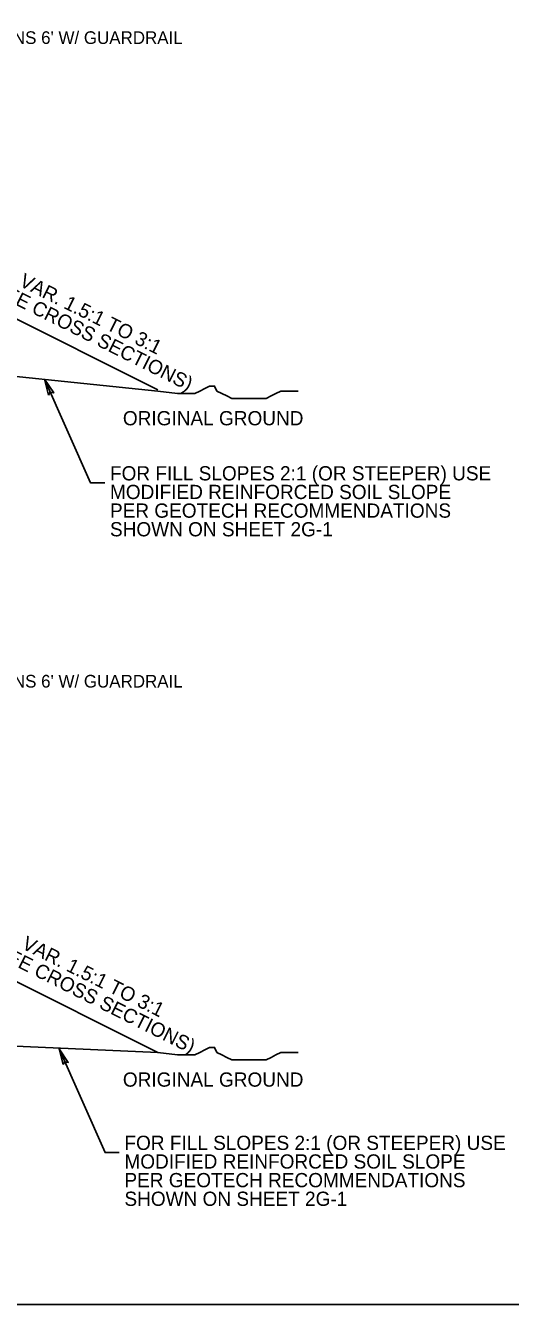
# Model space of a CAD drawing. Extents: x 1548135 to 1549339, y 868664 to 869085.
# Drawn here: x 1548242.4 to 1548268, y 868801.8 to 868869.2 of the extents above; entities that cross this region are included whole.
import ezdxf

# ---------------------------------------------------------------- set-up
doc = ezdxf.new("R2010")
doc.units = 0
for name, color, linetype in [('Default', 7, 'Continuous'), ('Prop Dimension', 7, 'Continuous'), ('Sheet_Data_Field_CELL', 7, 'Continuous'), ('Typical Hinge Slope Interstate CELL', 7, 'Continuous'), ('Typical Text General CELL', 7, 'Continuous')]:
    doc.layers.add(name, color=color, linetype=linetype)

msp = doc.modelspace()

# ---------------------------------------------------------------- linework, layer by layer
at = {"layer": 'Default'}
msp.add_lwpolyline([(1548135.05, 868911.824), (1548305.05, 868911.824), (1548305.05, 868801.824), (1548135.05, 868801.824)], close=True, dxfattribs=at)
at = {"layer": 'Prop Dimension'}
for p, q in [((1548249.386, 868850.034), (1548238.748, 868855.353)), ((1548249.386, 868815.108), (1548238.748, 868820.427))]:
    msp.add_line(p, q, dxfattribs=at)
for points in [[(1548249.386, 868849.971), (1548250.424, 868849.842), (1548250.683, 868849.842), (1548251.072, 868849.842), (1548251.332, 868849.842), (1548251.591, 868849.971), (1548251.85, 868850.101), (1548252.11, 868850.231), (1548252.369, 868850.231), (1548252.499, 868849.971), (1548252.759, 868849.842), (1548253.018, 868849.712), (1548253.277, 868849.583), (1548253.537, 868849.583), (1548253.796, 868849.583), (1548254.055, 868849.583), (1548254.315, 868849.583), (1548254.574, 868849.583), (1548254.833, 868849.583), (1548255.093, 868849.583), (1548255.352, 868849.712), (1548255.611, 868849.842), (1548255.871, 868849.971), (1548256.26, 868849.971), (1548256.52, 868849.971), (1548256.779, 868849.971)], [(1548249.386, 868815.108), (1548250.424, 868814.979), (1548250.683, 868814.979), (1548251.072, 868814.979), (1548251.332, 868814.979), (1548251.591, 868815.108), (1548251.85, 868815.238), (1548252.11, 868815.369), (1548252.369, 868815.369), (1548252.499, 868815.108), (1548252.759, 868814.979), (1548253.018, 868814.849), (1548253.277, 868814.72), (1548253.537, 868814.72), (1548253.796, 868814.72), (1548254.055, 868814.72), (1548254.315, 868814.72), (1548254.574, 868814.72), (1548254.833, 868814.72), (1548255.093, 868814.72), (1548255.352, 868814.849), (1548255.611, 868814.979), (1548255.871, 868815.108), (1548256.26, 868815.108), (1548256.519, 868815.108), (1548256.779, 868815.108)]]:
    msp.add_lwpolyline(points, dxfattribs=at)
at = {"layer": 'Typical Hinge Slope Interstate CELL'}
for points in [[(1548220.737, 868855.904), (1548224.718, 868855.321), (1548227.45, 868854.175), (1548230.353, 868852.494), (1548237.134, 868851.24), (1548249.386, 868849.971)], [(1548243.403, 868850.591), (1548245.828, 868845.126), (1548246.579, 868845.126)], [(1548206.737, 868821.258), (1548210.718, 868820.675), (1548213.45, 868819.529), (1548216.353, 868817.848), (1548223.146, 868816.357), (1548235.151, 868815.732), (1548249.386, 868815.108)], [(1548244.166, 868815.297), (1548246.591, 868809.832), (1548247.342, 868809.832)]]:
    msp.add_lwpolyline(points, dxfattribs=at)
for points in [[(1548243.613, 868849.761), (1548243.403, 868850.591), (1548243.884, 868849.876), (1548243.704, 868849.914)], [(1548244.376, 868814.467), (1548244.166, 868815.297), (1548244.647, 868814.582), (1548244.467, 868814.62)]]:
    msp.add_lwpolyline(points, close=True, dxfattribs=at)

# ---------------------------------------------------------------- texts
at = {"layer": 'Sheet_Data_Field_CELL'}
for s, p in [('(SEE CROSS SECTIONS)', (1548240.316, 868855.289)), ('VAR. 1.5:1 TO 3:1', (1548242.016, 868855.538)), ('VAR. 1.5:1 TO 3:1', (1548242.147, 868820.609)), ('(SEE CROSS SECTIONS)', (1548240.447, 868820.36))]:
    msp.add_text(s, height=0.75, rotation=333.43403, dxfattribs=at).set_placement(p)
for p in [(1548247.534, 868848.166), (1548247.534, 868813.303)]:
    msp.add_text('ORIGINAL GROUND', height=0.75, dxfattribs=at).set_placement(p)
at = {"layer": 'Typical Hinge Slope Interstate CELL'}
for s, p in [('FOR FILL SLOPES 2:1 (OR STEEPER) USE', (1548246.853, 868845.262)), ('MODIFIED REINFORCED SOIL SLOPE', (1548246.853, 868844.279)), ('PER GEOTECH RECOMMENDATIONS', (1548246.853, 868843.296)), ('SHOWN ON SHEET 2G-1', (1548246.853, 868842.313)), ('FOR FILL SLOPES 2:1 (OR STEEPER) USE', (1548247.616, 868809.968)), ('MODIFIED REINFORCED SOIL SLOPE', (1548247.616, 868808.985)), ('PER GEOTECH RECOMMENDATIONS', (1548247.616, 868808.002)), ('SHOWN ON SHEET 2G-1', (1548247.616, 868807.019))]:
    msp.add_text(s, height=0.75, dxfattribs=at).set_placement(p)
at = {"layer": 'Typical Text General CELL'}
for p in [(1548238.304, 868868.268), (1548238.304, 868834.342)]:
    msp.add_text("* REMAINS 6' W/ GUARDRAIL", height=0.66824, dxfattribs=at).set_placement(p)

doc.saveas('drawing.dxf')
